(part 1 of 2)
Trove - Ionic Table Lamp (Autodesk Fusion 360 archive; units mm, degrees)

design "Marble Base - Ionic Table Lamp - 120V" references "Marble Base - Silicone Gasket", "Balon v2", "Chinois", "Neoprene Pad", "Rubber Grommet", "Marble Base - Plastic Insert", "2-Pole Plug End", "Trove - TL", "Arca Tall", "T9 - Bulb", "Facet Petite", "T9-5In"
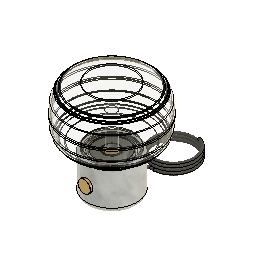
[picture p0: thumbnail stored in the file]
sketch "Sketch1" plane through (0, 0, 0) normal (0, 0, 1) x axis (1, 0, 0)
  circle C1 centre (0, 0) radius 63.5
  point P1 (0, 0)
  point P2 (0, 0)
  coincident P1 P2
extrude "Extrude1" new body sketch "Sketch1" along normal blind 101.6 bodies "Marble Base"
sketch "Sketch2" plane through (0, 0, 101.6) normal (0, 0, 1) x axis (-1, 0, 0)
  circle C1 centre (0, 0) radius 63.5
  circle C2 centre (0, 0) radius 53.975
  concentric C1 C2
  dimension "d3" diameter C2 = 107.95
extrude "Extrude2" cut sketch "Sketch2" profile of C2 against normal blind 34.925
sketch "Sketch3" plane through (0, 0, 66.675) normal (0, 0, 1) x axis (-1, 0, 0)
  circle C1 centre (0, 0) radius 53.975
  circle C2 centre (0, 0) radius 49.276
  point P1 (0, 0)
  point P3 (0, 0)
  coincident P1 P3
  dimension "d6" diameter C2 = 98.552
extrude "Extrude3" cut sketch "Sketch3" profile of C2 against normal blind 45.72
sketch "Sketch4" plane through (0, 0, 0) normal (0, 1, 0) x axis (1, 0, 0)
  circle C1 centre (0, -50.8) radius 3.81
  dimension "d9" diameter C1 = 7.62
extrude "Extrude4" cut sketch "Sketch4" against normal blind 127
sketch "Sketch5" plane through (0, 0, 0) normal (0, 1, 0) x axis (1, 0, 0)
  line L1 (0, -25.4) -> (0, 0)
  line L2 (0, -30.48) -> (0, -25.4)
  circle C1 centre (0, -30.48) radius 5.08
  point P1 (0, 0)
  point P2 (0, 0)
  point P4 (0, -30.48)
  point P5 (0, -30.48)
  coincident P1 P2
  vertical L1
  parallel L1 L2
  coincident P4 P5
  dimension "d12" diameter C1 = 10.16
extrude "Extrude5" cut sketch "Sketch5" profile of C1 along normal blind 114.3
fillet "Fillet1" radius 6.35 3.175 4.064
derived_base_feature "Derived Base Feature1" bodies "Rotary Switch"
derived_base_feature "Derived Base Feature1" bodies "Coiled - SVT (Blk Fabric)"
derived_base_feature "Derived Base Feature1" bodies "Glass Globe"
derived_base_feature "Derived Base Feature1" bodies "Metal Housing"
derived_base_feature "Derived Base Feature1" bodies "Metal Socket Cover"
derived_base_feature "Derived Base Feature1" bodies "Porcelain Socket"
derived_base_feature "Derived Base Feature1" bodies "Brass Dial - Dimmer Knob"
component_from_bodies "Body->Comp1"
offset_faces "OffsetFaces1" distance 12.7
offset_faces "OffsetFaces2" distance -12.7
derived_base_feature "Derived Base Feature1" bodies "Solitaire Petite"
move "Move1"
offset_faces "OffsetFaces1" distance 20.32
move "Move2"
extrude "Extrude6" add of existing geometry blind 25.4
offset_faces "OffsetFaces2" distance -3.81
fillet "Fillet2" radius 2.54
move "Move3"
derived_base_feature "Derived Base Feature2" bodies "Facet Petite"
move "Move4"
offset_faces "OffsetFaces1" distance 2.54
move "Move1"
derived_base_feature "Derived Base Feature1" bodies "Body1"
derived_base_feature "Derived Base Feature1" bodies "Body1"
derived_base_feature "Derived Base Feature1" bodies "Body1"
derived_base_feature "Derived Base Feature1" bodies "Body1"
derived_base_feature "Derived Base Feature1" bodies "Body1"
derived_base_feature "Derived Base Feature1" bodies "Body1", "Body2"
derived_base_feature "Derived Base Feature1" bodies "Body1"
position "Position1"
external_derived "ExternalDerived5" bodies "Plastic Insert"
derived_instance "DerivedInstance15"
offset_faces "OffsetFaces1" distance 3.81
offset_faces "OffsetFaces2" distance -1.0414
move "Move6"
external_derived "ExternalDerived6" sketch "Sketch3" bodies "Silicone Gasket"
derived_instance "DerivedInstance16"
offset_faces "OffsetFaces3" distance -10.795
move "Move1"
move_face "MoveFace1"
position "Position2"
position "Position3"
position "Position4"
position "Position5"
move "Move2"
position "Position6"
offset_faces "OffsetFaces2" distance -7.62
chamfer "Chamfer1" distance 0.381
remove_instance "RemoveInstance1"
remove_instance "RemoveInstance2"
remove_instance "RemoveInstance3"
remove_instance "RemoveInstance4"
move "Move1"
derived_base_feature "Derived Base Feature5" bodies "Oculo Petite"
align "Align1"
external_derived "ExternalDerived8"
derived_base_feature "Derived Base Feature7" bodies "Balon v2"
derived_base_feature "Derived Base Feature8" bodies "Balon v3"
align "Align3"
align "Align4"
external_derived "ExternalDerived10"
component_insert "Component Insert1"
position "Position7"
position "Position8"
derived_base_feature "Derived Base Feature11" bodies "Trove - TL"
move "Move10"
move "Move11"
remove_instance "RemoveInstance5"
split "Split1" bodies "Trove - TL (1)"
remove_body "RemoveBody2"
remove_body "RemoveBody3"
external_derived "ExternalDerived13" bodies "Trove - TL"
derived_instance "DerivedInstance20"
remove_body "RemoveBody4"
remove_body "RemoveBody5"
component_insert "Component Insert2"
component_insert "Component Insert3"
component_from_bodies "Body->Comp2"
remove_body "RemoveBody7"
move "Move12"
move "Move13"
sketch "Sketch6" plane through (0, 0, 97.917) normal (0, 0, 1) x axis (-1, 0, 0)
  circle C1 centre (0, 0) radius 41.275
  circle C2 centre (0, 0) radius 19.685
  arc A1 centre (0, 0) radius 29.3982 clockwise from (-27.6283, 10.0466) to (27.6283, 10.0466)
  arc A2 centre (0, 0) radius 26.2232 clockwise from (-24.6444, 8.9616) to (24.6444, 8.9616)
  arc A3 centre (0, 0) radius 32.5732 clockwise from (-30.6121, 11.1317) to (30.6121, 11.1317)
  arc A4 centre (0, 0) radius 35.7482 clockwise from (-33.596, 12.2167) to (33.596, 12.2167)
  point P1 (0, 0)
  point P3 (0, 0)
  coincident P1 P3
  dimension "d37" = -3.175
  dimension "d38" = 3.175
  dimension "d39" = 6.35
  dimension "d40" Text1-Height = 2.54
  dimension "d41" Text2-Height = 2.54
  dimension "d42" Text3-Height = 2.54
  dimension "d43" Text4-Height = 2.54
extrude "Extrude1" cut sketch "Sketch6" against normal blind 0.254
external_derived "ExternalDerived14" bodies "Rubber Grommet"
derived_instance "DerivedInstance19"
external_derived "ExternalDerived15" bodies "2-Pole Plug End"
derived_instance "DerivedInstance18"
external_derived "ExternalDerived16" bodies "Neoprene Pad"
derived_instance "DerivedInstance17"
position "Position9"
position "Position10"
position "Position11"
position "Position12"
external_derived "ExternalDerived17" bodies "Chinois"
derived_instance "DerivedInstance21"
position "Position13"
move "Move3"
remove_body "RemoveBody8"
component_insert "Component Insert4"
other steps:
derived_base_feature "Derived Base Feature1" bodies "Trove - TL"
derived_base_feature "Derived Base Feature1" bodies "Chinois"
derived_base_feature "Derived Base Feature1" bodies "Rubber Grommet"
derived_base_feature "Derived Base Feature1" bodies "2-Pole Plug End"
derived_base_feature "Derived Base Feature1" bodies "Neoprene Pad"
move "Move1"
base_feature "Base Feature1" bodies "Oculo Petite", "Arca Petite"
derived_base_feature "Derived Base Feature1" bodies "Plastic Insert"
derived_base_feature "Derived Base Feature1" bodies "Silicone Gasket"
base_feature "Base Feature1" bodies "Marble Base"
move "Move8"
derived_base_feature "Derived Base Feature"
create_component "CreateComponent1"
create_component "CreateComponent2"
create_component "CreateComponent3"
create_component "CreateComponent4"
create_component "CreateComponent5"
create_component "CreateComponent6"
create_component "CreateComponent7"
create_component "CreateComponent8"
remove_body "RemoveBody1"
create_component "CreateComponent9"
create_component "CreateComponent10"
create_component "CreateComponent11"
create_component "CreateComponent12"
create_component "CreateComponent13"
create_component "CreateComponent14"
create_component "CreateComponent15"
create_component "CreateComponent16"
create_component "CreateComponent17"
create_component "CreateComponent18"
remove_body "RemoveBody6"
create_component "CreateComponent19"
create_component "CreateComponent20"
create_component "CreateComponent21"
create_component "CreateComponent22"
create_component "CreateComponent23"
named bodies: "Marble Base", "Rotary Switch", "Coiled - SVT (Blk Fabric)", "Glass Globe", "Metal Housing", "Metal Socket Cover", "Porcelain Socket", "Brass Dial - Dimmer Knob", "Solitaire Petite", "Facet Petite", "Body1", "Body2", "Plastic Insert", "Silicone Gasket", "Oculo Petite", "Balon v2", "Balon v3", "Trove - TL", "Trove - TL (1)", "Arca Petite", "Neoprene Pad", "2-Pole Plug End", "Rubber Grommet", "Chinois"

design "Neoprene Pad"
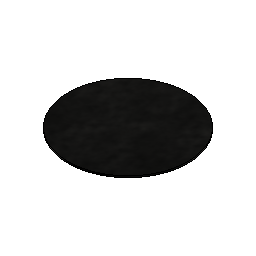
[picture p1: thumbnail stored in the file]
sketch "Sketch1" plane through (0, 0, 0) normal (0, 0, 1) x axis (1, 0, 0)
  circle C1 centre (0, 0) radius 57.15
  point P1 (0, 0)
  point P2 (0, 0)
  coincident P1 P2
extrude "Extrude1" new body sketch "Sketch1" along normal blind 1.5875 bodies "Neoprene Pad"
component_from_bodies "Body->Comp"
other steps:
base_feature "Base Feature" bodies "Neoprene Pad"
create_component "CreateComponent1"
remove_body "RemoveBody1"
named bodies: "Neoprene Pad"

design "T9 - Bulb"
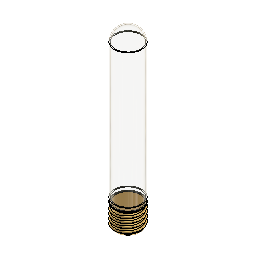
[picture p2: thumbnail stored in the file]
sketch "Sketch1" plane through (0, 0, 0) normal (0, 1, 0) x axis (1, 0, 0)
  line L1 (0, -166.37) -> (0, 0)
  line L2 (13.97, -13.97) -> (13.97, -152.4)
  line L3 (-13.97, -152.4) -> (-13.97, -13.97)
  line L4 (0, 0) -> (0, -166.37)
  line L5 (12.97, -13.97) -> (12.97, -152.4)
  line L6 (-12.97, -152.4) -> (-12.97, -13.97)
  line L7 (-12.3978, -10.16) -> (-13.4404, -10.16)
  line L8 (13.4404, -10.16) -> (12.3978, -10.16)
  arc A1 centre (0, -152.4) radius 13.97 clockwise from (13.97, -152.4) to (-13.97, -152.4)
  arc A2 centre (0, -152.4) radius 12.97 clockwise from (12.97, -152.4) to (-12.97, -152.4)
  arc A3 centre (0, -13.97) radius 13.97 clockwise from (13.4404, -10.16) to (13.97, -13.97)
  arc A4 centre (0, -13.97) radius 13.97 clockwise from (-13.97, -13.97) to (-13.4404, -10.16)
  arc A5 centre (0, -13.97) radius 12.97 clockwise from (12.3978, -10.16) to (12.97, -13.97)
  arc A6 centre (0, -13.97) radius 12.97 clockwise from (-12.97, -13.97) to (-12.3978, -10.16)
  point P1 (0, 0)
  point P2 (0, 0)
  point P3 (0, -166.37)
  point P10 (0, 0)
  point P17 (13.4404, -10.16)
  point P19 (12.3978, -10.16)
  point P4 (13.97, -152.4)
  point P5 (13.97, -13.97)
  coincident P1 P2
  vertical L1
  tangent L2 A3
  tangent L3 A3
  parallel L2 L3
  tangent L3 A1
  tangent L2 A1
  midpoint P3 A1
  coincident P1 P10
  perpendicular L1 L7
  coincident P17 L7
  concentric A3 A4
  coincident P10 A3
  concentric A1 A2
  tangent L5 A2
  tangent L5 A5
  tangent L6 A5
  tangent L6 A2
  coincident P19 L7
  concentric A5 A6
  collinear L7 L8
  dimension "d6" distance L2 L3 = 27.94
  dimension "d7" distance P4 P5 = 138.43
revolve "Revolve1" sketch "Sketch1" AlongAngle 360 bodies "T9"
derived_base_feature "Derived Base Feature" bodies "E26 Base"
align "Align1"
move "Move1"
component_from_bodies "Body->Comp1"
component_from_bodies "Body->Comp2"
copy_paste "CutPaste1"
copy_paste "CutPaste2"
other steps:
base_feature "Base Feature1" bodies "T9"
base_feature "Base Feature1" bodies "E26 Base"
create_component "CreateComponent1"
create_component "CreateComponent2"
remove_body "RemoveBody1"
create_component "CreateComponent3"
remove_body "RemoveBody2"
remove_instance "RemoveInstance1"
remove_instance "RemoveInstance2"
named bodies: "T9", "E26 Base"

design "Marble Base - Silicone Gasket"
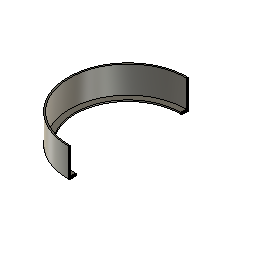
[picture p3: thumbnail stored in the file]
sketch "Sketch1" plane through (0, 0, 0) normal (0, 0, 1) x axis (1, 0, 0)
  circle C1 centre (0, 0) radius 53.34
  point P1 (0, 0)
  point P2 (0, 0)
  coincident P1 P2
extrude "Extrude1" new body sketch "Sketch1" along normal blind 25.4 bodies "Silicone Gasket"
shell "Shell1" innerThickness 1.27
sketch "Sketch2" plane through (0, 0, 1.27) normal (0, 0, 1) x axis (-1, 0, 0)
  circle C1 centre (0, 0) radius 52.07
  circle C2 centre (0, 0) radius 46.99
  concentric C1 C2
extrude "Extrude2" cut sketch "Sketch2" profile of C2 against normal blind 12.7
component_from_bodies "Body->Comp"
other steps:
base_feature "Base Feature" bodies "Silicone Gasket"
create_component "CreateComponent1"
remove_body "RemoveBody1"
named bodies: "Silicone Gasket"

design "2-Pole Plug End"
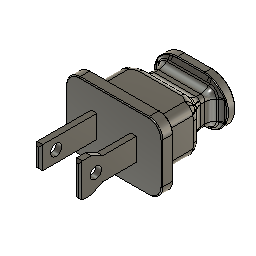
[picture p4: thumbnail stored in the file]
sketch "Sketch1" plane through (0, 0, 0) normal (0, 1, 0) x axis (1, 0, 0)
  line L1 (9.6837, 9.525) -> (-9.6837, 9.525)
  line L2 (13.4938, -5.715) -> (13.4938, 5.715)
  line L3 (-9.6837, -9.525) -> (9.6837, -9.525)
  line L4 (-13.4937, 5.715) -> (-13.4937, -5.715)
  line L5 (13.4938, -9.525) -> (-13.4937, 9.525)
  line L6 (-13.4937, -9.525) -> (13.4938, 9.525)
  arc A1 centre (-9.6837, -5.715) radius 3.81 clockwise from (-9.6837, -9.525) to (-13.4937, -5.715)
  arc A2 centre (9.6837, -5.715) radius 3.81 clockwise from (13.4938, -5.715) to (9.6837, -9.525)
  arc A3 centre (9.6837, 5.715) radius 3.81 clockwise from (9.6837, 9.525) to (13.4938, 5.715)
  arc A4 centre (-9.6837, 5.715) radius 3.81 clockwise from (-13.4937, 5.715) to (-9.6837, 9.525)
  point P6 (0, 0)
  point P1 (0, 0)
  point P5 (-13.4937, -9.525)
  point P4 (13.4938, -9.525)
  point P3 (13.4938, 9.525)
  point P2 (-13.4937, 9.525)
  horizontal L1
  perpendicular L1 L2
  parallel L1 L3
  parallel L2 L4
  coincident L5 P6
  coincident L6 P6
  coincident P1 P6
  coincident P5 L4
  coincident P5 L3
  tangent L4 A1
  tangent L3 A1
  coincident P4 L3
  coincident P4 L2
  tangent L3 A2
  tangent L2 A2
  equal A1 A2
  coincident P3 L2
  coincident P3 L1
  tangent L2 A3
  tangent L1 A3
  equal A1 A3
  coincident P2 L1
  coincident P2 L4
  tangent L1 A4
  tangent L4 A4
  equal A1 A4
  dimension "d1" distance P4 P5 = 26.9875
  dimension "d2" distance P2 P5 = 19.05
  dimension "d3" radius A1 = 3.81
extrude "Extrude1" new body sketch "Sketch1" profile of L1 L2 L3 L4 A1 A2 A3 A4 along normal blind 3.175
sketch "Sketch2" plane through (0, 3.175, 0) normal (0, 1, 0) x axis (-1, 0, 0)
  line L1 (9.6837, -9.525) -> (-9.6837, -9.525)
  line L2 (13.4937, 5.715) -> (13.4937, -5.715)
  line L3 (-9.6837, 9.525) -> (9.6837, 9.525)
  line L4 (-13.4938, -5.715) -> (-13.4938, 5.715)
  line L5 (10.16, -6.35) -> (-10.16, -6.35)
  line L6 (10.16, 6.35) -> (10.16, -6.35)
  line L7 (-10.16, 6.35) -> (10.16, 6.35)
  line L8 (-10.16, -6.35) -> (-10.16, 6.35)
  line L9 (10.16, 6.35) -> (-10.16, -6.35)
  line L10 (-10.16, 6.35) -> (10.16, -6.35)
  arc A1 centre (-9.6837, -5.715) radius 3.81 clockwise from (-9.6837, -9.525) to (-13.4938, -5.715)
  arc A2 centre (9.6837, -5.715) radius 3.81 clockwise from (13.4937, -5.715) to (9.6837, -9.525)
  arc A3 centre (9.6837, 5.715) radius 3.81 clockwise from (9.6837, 9.525) to (13.4937, 5.715)
  arc A4 centre (-9.6837, 5.715) radius 3.81 clockwise from (-13.4938, 5.715) to (-9.6837, 9.525)
  point P18 (0, 0)
  point P1 (0, 0)
  horizontal L5
  perpendicular L5 L6
  parallel L5 L7
  parallel L6 L8
  coincident L9 P18
  coincident L10 P18
  coincident P1 P18
extrude "Extrude2" add sketch "Sketch2" profile of L5 L6 L7 L8 along normal blind 9.525
sketch "Sketch3" plane through (0, 12.7, 0) normal (0, 1, 0) x axis (-1, 0, 0)
  line L1 (-10.16, -6.35) -> (-10.16, 6.35)
  line L2 (10.16, -6.35) -> (-10.16, -6.35)
  line L3 (10.16, 6.35) -> (10.16, -6.35)
  line L4 (-10.16, 6.35) -> (10.16, 6.35)
  line L5 (-7.1437, 3.9688) -> (7.1437, 3.9688)
  line L6 (-7.1437, -3.9688) -> (-7.1437, 3.9688)
  line L7 (7.1437, -3.9688) -> (-7.1437, -3.9688)
  line L8 (7.1437, 3.9688) -> (7.1437, -3.9688)
  line L9 (-7.1437, -3.9688) -> (7.1437, 3.9688)
  line L10 (7.1437, -3.9688) -> (-7.1437, 3.9688)
  point P10 (0, 0)
  point P1 (0, 0)
  point P8 (-7.1437, -3.9688)
  point P9 (7.1437, -3.9688)
  point P7 (-7.1437, 3.9688)
  horizontal L5
  perpendicular L5 L6
  parallel L5 L7
  parallel L6 L8
  coincident L9 P10
  coincident L10 P10
  coincident P1 P10
  dimension "d8" distance P8 P9 = 14.2875
  dimension "d9" distance P7 P8 = 7.9375
extrude "Extrude3" add sketch "Sketch3" profile of L5 L6 L7 L8 along normal blind 11.1125
fillet "Fillet1" radius 2.286 1.27 0.254
chamfer "Chamfer1" distance 3.429
fillet "Fillet2" radius 2.54 1.905
sketch "Sketch4" plane through (0, 23.8125, 0) normal (0, 1, 0) x axis (-1, 0, 0)
  line L1 (-7.1437, -2.6987) -> (-7.1437, 2.6987)
  line L2 (5.8737, -3.9688) -> (-5.8737, -3.9688)
  line L3 (7.1437, 2.6987) -> (7.1437, -2.6987)
  line L4 (-5.8737, 3.9688) -> (5.8737, 3.9688)
  line L5 (-3.81, 6.604) -> (3.81, 6.604)
  line L6 (3.81, -6.604) -> (-3.81, -6.604)
  line L7 (-10.414, 0) -> (10.414, 0)
  arc A1 centre (-5.8737, 2.6987) radius 1.27 clockwise from (-7.1437, 2.6987) to (-5.8737, 3.9688)
  arc A2 centre (-5.8737, -2.6987) radius 1.27 clockwise from (-5.8737, -3.9688) to (-7.1437, -2.6987)
  arc A3 centre (5.8737, -2.6987) radius 1.27 clockwise from (7.1437, -2.6987) to (5.8737, -3.9688)
  arc A4 centre (5.8737, 2.6987) radius 1.27 clockwise from (5.8737, 3.9688) to (7.1437, 2.6987)
  arc A5 centre (-3.81, 0) radius 6.604 clockwise from (-3.81, -6.604) to (-3.81, 6.604)
  arc A6 centre (3.81, 0) radius 6.604 clockwise from (3.81, 6.604) to (3.81, -6.604)
  point P20 (10.414, 0)
  point P21 (-10.414, 0)
  tangent L5 A5
  tangent A5 L6
  parallel L5 L6
  tangent L6 A6
  tangent L5 A6
  midpoint A6 P20
  midpoint A5 P21
  perpendicular L1 L7
extrude "Extrude4" add sketch "Sketch4" profile of A1 L1 A2 L2 A3 L3 A4 L4 L5 A5 L6 A6 against normal blind 2.286
chamfer "Chamfer2" distance 1.778
fillet "Fillet3" radius 1.778
fillet "Fillet4" radius 0.254
fillet "Fillet5" radius 0.254
fillet "Fillet6" radius 0.254
fillet "Fillet7" radius 3.175
sketch "Sketch5" plane through (0, 0, 0) normal (0, -1, 0) x axis (1, 0, 0)
  line L1 (-13.2397, -5.715) -> (-13.2397, 5.715)
  line L2 (9.6837, -9.271) -> (-9.6837, -9.271)
  line L3 (13.2397, 5.715) -> (13.2397, -5.715)
  line L4 (-9.6837, 9.271) -> (9.6837, 9.271)
  line L5 (-6.35, -3.175) -> (-6.35, 3.175)
  line L6 (6.35, 3.175) -> (-6.35, -3.175)
  line L7 (-6.35, 3.175) -> (6.35, -3.175)
  line L8 (-4.7625, 3.175) -> (-6.35, 3.175)
  line L9 (-4.7625, -3.175) -> (-4.7625, 3.175)
  line L10 (-6.35, -3.175) -> (-4.7625, -3.175)
  line L11 (-6.35, 3.175) -> (-6.35, -3.175)
  line L12 (0, -3.302) -> (0, 3.81)
  line L13 (4.7625, -3.175) -> (4.7625, 3.175)
  line L14 (4.7625, 3.175) -> (6.35, 3.175)
  line L15 (6.35, -3.175) -> (6.35, 3.175)
  line L16 (6.35, -3.175) -> (4.7625, -3.175)
  arc A1 centre (-9.6837, 5.715) radius 3.556 clockwise from (-13.2397, 5.715) to (-9.6837, 9.271)
  arc A2 centre (-9.6837, -5.715) radius 3.556 clockwise from (-9.6837, -9.271) to (-13.2397, -5.715)
  arc A3 centre (9.6837, -5.715) radius 3.556 clockwise from (13.2397, -5.715) to (9.6837, -9.271)
  arc A4 centre (9.6837, 5.715) radius 3.556 clockwise from (9.6837, 9.271) to (13.2397, 5.715)
  point P18 (0, 0)
  point P1 (0, 0)
  point P14 (-6.35, -3.175)
  point P27 (6.35, -3.175)
  point P17 (-6.35, 3.175)
  point P26 (6.35, 3.175)
  point P19 (-4.7625, 3.175)
  point P24 (4.7625, 3.175)
  point P20 (-4.7625, -3.175)
  point P25 (4.7625, -3.175)
  point P21 (-6.35, -3.175)
  point P28 (6.35, -3.175)
  point P15 (6.35, -3.175)
  point P16 (6.35, 3.175)
  coincident L6 P18
  coincident L7 P18
  coincident P1 P18
  horizontal L8
  vertical L9
  horizontal L10
  vertical L11
  vertical L12
  symmetric P14 L12 P27
  symmetric P17 L12 P26
  symmetric P19 L12 P24
  symmetric P20 L12 P25
  symmetric P21 L12 P28
  dimension "d36" distance P15 P16 = 6.35
  dimension "d37" distance P17 P19 = 1.5875
extrude "Extrude5" add sketch "Sketch5" profile of L5 L8 L9 L10 L11 L13 L14 L15 L16 along normal blind 15.875
sketch "Sketch7" plane through (0, 0, 3.175) normal (0, 0, 1) x axis (-1, 0, 0)
  line L1 (-4.7625, 0) -> (-6.35, 0)
  line L2 (-4.7625, 15.875) -> (-4.7625, 0)
  line L3 (-6.35, 15.875) -> (-4.7625, 15.875)
  line L4 (-6.35, 0) -> (-6.35, 15.875)
  line L5 (-4.7625, 15.875) -> (-6.35, 15.875)
  line L6 (-4.7625, 9.525) -> (-4.7625, 15.875)
  line L7 (-6.35, 9.525) -> (-4.7625, 9.525)
  line L8 (-6.35, 15.875) -> (-6.35, 9.525)
  point P5 (-6.35, 15.875)
  point P6 (-6.35, 15.875)
  point P9 (-6.35, 9.525)
  horizontal L5
  vertical L6
  horizontal L7
  vertical L8
  coincident P5 P6
  dimension "d45" distance P6 P9 = 6.35
extrude "Extrude7" add sketch "Sketch7" profile of L2 L3 L4 L5 L6 L7 L8 against normal blind 7.9375 and along normal blind 1.5875
chamfer "Chamfer3" distance 0.508
chamfer "Chamfer4" distance 0.635 distance 0.635
sketch "Sketch6" plane through (6.35, 0, 0) normal (1, 0, 0) x axis (0, 1, 0)
  line L1 (0, -3.175) -> (-9.525, -3.175)
  line L2 (0, 3.175) -> (0, -3.175)
  line L3 (-9.525, 3.175) -> (0, 3.175)
  line L4 (-15.367, -4.6355) -> (-15.367, 4.6355)
  line L5 (-11.43, 0) -> (-16.002, 0)
  line L6 (-9.525, -4.7625) -> (-15.24, -4.7625)
  line L7 (-9.525, -3.175) -> (-9.525, -4.7625)
  line L8 (-9.525, 4.7625) -> (-9.525, 3.175)
  line L9 (-15.24, 4.7625) -> (-9.525, 4.7625)
  line L10 (-15.24, -4.7625) -> (-15.367, -4.6355)
  line L11 (-15.367, 4.6355) -> (-15.24, 4.7625)
  circle C1 centre (-11.43, 0) radius 1.5875
  point P9 (-11.43, 0)
  point P10 (-11.43, 0)
  perpendicular L4 L5
  coincident P9 P10
  dimension "d42" diameter C1 = 3.175
extrude "Extrude6" cut sketch "Sketch6" profile of C1 against normal blind 20.32
chamfer "Chamfer5" distance 3.175 distance 1.5875 distance 3.175 distance 1.5875
component_from_bodies "Body->Comp"
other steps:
base_feature "Base Feature" bodies "2-Pole Plug End"
create_component "CreateComponent1"
remove_body "RemoveBody1"
named bodies: "2-Pole Plug End"

design "Facet Petite"
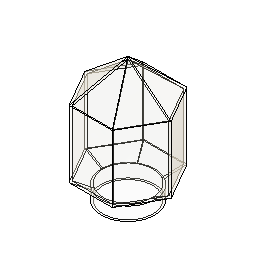
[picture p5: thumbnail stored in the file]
sketch "Sketch7" plane through (0, 0, 0) normal (1, 0, 0) x axis (0, 1, 0)
sketch "Sketch8" plane through (0, 0, 0) normal (0, 0, 1) x axis (1, 0, 0)
  circle C1 centre (0, 0) radius 50.8
  point P1 (0, 0)
  point P2 (0, 0)
  coincident P1 P2
  dimension "d17" diameter C1 = 101.6
extrude "Extrude5" new body sketch "Sketch8" along normal blind 25.4 and against normal blind 25.4
work_plane "WorkPlane1" AlongDistance 17.78
sketch "Sketch10" plane through (0, 0, 25.4) normal (0, 0, 1) x axis (-1, 0, 0)
  circle C1 centre (0, 0) radius 50.8
sketch "Sketch12" plane through (0, 0, 43.18) normal (0, 0, 1) x axis (1, 0, 0)
  line L1 (-82.1223, 0) -> (-41.0612, 71.12)
  line L2 (-41.0612, -71.12) -> (-82.1223, 0)
  line L3 (41.0612, -71.12) -> (-41.0612, -71.12)
  line L4 (82.1223, 0) -> (41.0612, -71.12)
  line L5 (41.0612, 71.12) -> (82.1223, 0)
  line L6 (-41.0612, 71.12) -> (41.0612, 71.12)
  point P1 (0, 0)
  point P8 (0, 0)
  coincident P1 P8
  dimension "d22" distance P8 L6 = 71.12
sketch "Sketch15" plane through (0, 0, 0) normal (0, 1, 0) x axis (1, 0, 0)
  line L1 (53.7365, -21.6801) -> (82.1223, -43.18)
  line L2 (-50.8, -25.4) -> (-82.1223, -43.18)
  point P2 (82.1223, -43.18)
  point P3 (82.1223, -43.18)
  point P5 (-82.1223, -43.18)
  point P7 (-82.1223, -43.18)
  point P6 (-50.8, -25.4)
  point P8 (-50.8, -25.4)
  coincident P2 P3
  coincident P5 P7
  coincident P6 P8
sketch "Sketch17" plane through (0, 0, 25.4) normal (0, 0, 1) x axis (-1, 0, 0)
  line L1 (51.3255, 0) -> (0, 0)
  line L2 (73.3235, 0) -> (0, 0)
  line L3 (-41.0612, -71.12) -> (-25.4, -43.9941)
  line L4 (-36.6617, -63.5) -> (-25.4, -43.9941)
  line L5 (78.4305, 0) -> (0, 0)
  line L6 (41.0612, -71.12) -> (25.4, -43.9941)
  line L7 (25.4, 43.9941) -> (41.0612, 71.12)
  line L8 (73.3235, 0) -> (0, 0)
  line L9 (-25.4, 43.9941) -> (-41.0612, 71.12)
  line L10 (0, 0) -> (0, 0)
  circle C1 centre (0, 0) radius 50.8
  point P1 (0, 0)
  point P4 (0, 0)
  point P2 (-41.0612, -71.12)
  point P6 (-41.0612, -71.12)
  point P3 (0, 0)
  point P7 (0, 0)
  point P9 (-25.4, -43.9941)
  point P12 (41.0612, -71.12)
  point P13 (41.0612, -71.12)
  point P15 (25.4, -43.9941)
  point P16 (41.0612, 71.12)
  point P17 (41.0612, 71.12)
  point P18 (25.4, 43.9941)
  point P19 (-41.0612, 71.12)
  point P20 (-41.0612, 71.12)
  point P21 (0, 0)
  point P23 (-25.4, 43.9941)
  point P25 (0, 0)
  point P24 (0, 0)
  point P26 (0, 0)
  horizontal L1
  coincident P1 P4
  coincident P2 P6
  horizontal L2
  coincident P3 P7
  coincident C1 P9
  coincident P12 P13
  horizontal L5
  coincident C1 P15
  coincident P16 P17
  coincident C1 P18
  coincident P19 P20
  horizontal L8
  coincident P1 P21
  coincident C1 P23
  coincident P1 P25
  coincident P24 P26
extrude "Extrude6" new body sketch "Sketch12" along normal blind 127
work_plane "WorkPlane2" AlongDistance 66.04
sketch "Sketch18" plane through (0, 0, 236.22) normal (0, 0, 1) x axis (1, 0, 0)
  line L1 (41.0612, -71.12) -> (0, 0)
  line L2 (82.1223, 0) -> (0, 0)
  line L3 (41.0612, 71.12) -> (0, 0)
  line L4 (-41.0612, 71.12) -> (0, 0)
  line L5 (-82.1223, 0) -> (0, 0)
  line L6 (-41.0612, -71.12) -> (0, 0)
  point P1 (0, 0)
  point P3 (0, 0)
  point P2 (41.0612, -71.12)
  point P4 (41.0612, -71.12)
  point P6 (0, 0)
  point P5 (82.1223, 0)
  point P7 (82.1223, 0)
  point P9 (0, 0)
  point P8 (41.0612, 71.12)
  point P10 (41.0612, 71.12)
  point P12 (0, 0)
  point P11 (-41.0612, 71.12)
  point P13 (-41.0612, 71.12)
  point P15 (0, 0)
  point P14 (-82.1223, 0)
  point P16 (-82.1223, 0)
  point P18 (0, 0)
  point P17 (-41.0612, -71.12)
  point P19 (-41.0612, -71.12)
  coincident P1 P3
  coincident P2 P4
  coincident P1 P6
  coincident P5 P7
  coincident P1 P9
  coincident P8 P10
  coincident P1 P12
  coincident P11 P13
  coincident P1 P15
  coincident P14 P16
  coincident P1 P18
  coincident P17 P19
loft "Loft1"
loft "Loft2" sketch "Sketch17"
component_from_bodies "Body->Comp"
extrude "Extrude1" cut of existing geometry blind -25.4
shell "Shell2" innerThickness 3.81
fillet "Fillet1" radius 7.62
fillet "Fillet2" radius 6.35
fillet "Fillet3" radius 6.35
fillet "Fillet4" radius 6.35
fillet "Fillet5" radius 6.35
fillet "Fillet6" radius 6.35
fillet "Fillet7" radius 3.81
fillet "Fillet8" radius 6.35
fillet "Fillet9" radius 6.35
fillet "Fillet10" radius 6.35
fillet "Fillet11" radius 6.35
fillet "Fillet12" radius 6.35
fillet "Fillet13" radius 2.286
shell "Shell1" innerThickness 2.54
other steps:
base_feature "Base Feature"
create_component "CreateComponent3"
remove_body "RemoveBody2"

design "Chinois"
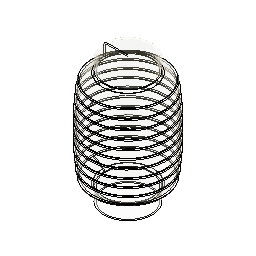
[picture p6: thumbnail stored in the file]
named bodies: "Chinois"

design "Marble Base - Plastic Insert"
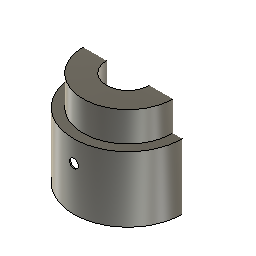
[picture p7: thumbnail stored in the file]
sketch "Sketch1" plane through (0, 0, 0) normal (0, 0, 1) x axis (1, 0, 0)
  circle C1 centre (0, 0) radius 50.038
  point P1 (0, 0)
  point P2 (0, 0)
  coincident P1 P2
  dimension "d1" diameter C1 = 100.076
extrude "Extrude1" new body sketch "Sketch1" along normal blind 72.898 bodies "Plastic Insert"
shell "Shell1" innerThickness 1.016
work_plane "WorkPlane1" AlongDistance 18.034
sketch "Sketch2" plane through (0, 0, 90.932) normal (0, 0, 1) x axis (1, 0, 0)
  circle C1 centre (0, 0) radius 20.701
  point P1 (0, 0)
  point P2 (0, 0)
  coincident P1 P2
  dimension "d6" diameter C1 = 41.402
extrude "Extrude2" add sketch "Sketch2" against normal blind 65.024
shell "Shell2" innerThickness 1.016
sketch "Sketch3" plane through (0, 0, 0) normal (0, 1, 0) x axis (1, 0, 0)
  line L1 (5.08, -20.32) -> (-5.08, -20.32)
  line L2 (5.08, 20.32) -> (5.08, -20.32)
  line L3 (-5.08, 20.32) -> (5.08, 20.32)
  line L4 (-5.08, -20.32) -> (-5.08, 20.32)
  line L5 (5.08, 20.32) -> (-5.08, -20.32)
  line L6 (-5.08, 20.32) -> (5.08, -20.32)
  point P6 (0, 0)
  point P1 (0, 0)
  horizontal L1
  perpendicular L1 L2
  parallel L1 L3
  parallel L2 L4
  coincident L5 P6
  coincident L6 P6
  coincident P1 P6
extrude "Extrude3" cut sketch "Sketch3" profile of L1 L2 L3 L4 along normal blind 91.44
sketch "Sketch4" plane through (0, 0, 0) normal (0, 1, 0) x axis (1, 0, 0)
  line L1 (0, -40.64) -> (0, 0)
  circle C1 centre (0, -40.64) radius 4.064
  point P1 (0, 0)
  point P2 (0, 0)
  point P3 (0, -40.64)
  point P4 (0, -40.64)
  coincident P1 P2
  vertical L1
  coincident P3 P4
  dimension "d12" diameter C1 = 8.128
work_plane "WorkPlane2" AlongDistance -91.44
sketch "Sketch5" plane through (0, -91.44, 0) normal (0, 1, 0) x axis (1, 0, 0)
  circle C1 centre (0, -40.64) radius 4.064
extrude "Extrude4" cut sketch "Sketch5" along normal blind 63.5
sketch "Sketch6" plane through (0, 0, 26.924) normal (0, 0, 1) x axis (-1, 0, 0)
  circle C1 centre (0, 0) radius 19.685
  circle C2 centre (0, 0) radius 5.461
  concentric C1 C2
  dimension "d16" diameter C2 = 10.922
extrude "Extrude5" cut sketch "Sketch6" profile of C2 against normal blind 15.24
sketch "Sketch7" plane through (0, 0, 72.898) normal (0, 0, 1) x axis (-1, 0, 0)
  circle C1 centre (0, 0) radius 20.701
  circle C2 centre (0, 0) radius 50.038
  circle C3 centre (0, 0) radius 20.701
  circle C4 centre (0, 0) radius 45.72
  point P1 (0, 0)
  point P3 (0, 0)
  point P4 (0, 0)
  coincident P1 P3
  coincident P1 P4
extrude "Extrude6" add sketch "Sketch7" profile of C1 C3 C4 along normal blind 18.034
sketch "Sketch8" plane through (0, 0, 71.882) normal (0, 0, -1) x axis (1, 0, 0)
  circle C1 centre (0, 0) radius 20.701
  circle C2 centre (0, 0) radius 49.022
  circle C3 centre (0, 0) radius 20.701
  circle C4 centre (0, 0) radius 44.704
  point P1 (0, 0)
  point P3 (0, 0)
  point P4 (0, 0)
  coincident P1 P3
  coincident P1 P4
  dimension "d21" diameter C4 = 89.408
extrude "Extrude7" cut sketch "Sketch8" profile of C1 C3 C4 against normal blind 17.78
extrude "Extrude8" add of existing geometry blind 9.398
extrude "Extrude9" cut of existing geometry blind -9.398
component_from_bodies "Body->Comp"
offset_faces "OffsetFaces1" distance 4.445
offset_faces "OffsetFaces2" distance -4.445
offset_faces "OffsetFaces3" distance 3.175
offset_faces "OffsetFaces4" distance 3.175
offset_faces "OffsetFaces5" distance 3.175
offset_faces "OffsetFaces6" distance -3.175
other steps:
base_feature "Base Feature" bodies "Plastic Insert"
create_component "CreateComponent1"
remove_body "RemoveBody1"
named bodies: "Plastic Insert"

design "Arca Tall"
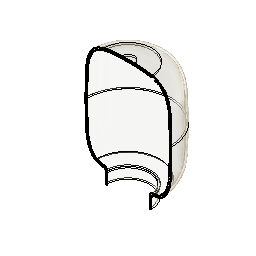
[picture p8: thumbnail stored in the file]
derived_base_feature "Derived Base Feature" bodies "Balon"
work_plane "WorkPlane1" AlongDistance 0
sketch "Sketch1" plane through (0, 0, 0) normal (0, 1, 0) x axis (1, 0, 0)
  line L1 (0, 317.5) -> (0, 2.9083)
  curve K1 (-82.9821, 124.2212) -> (-50.8, 237.8015)
  curve K2 (-51.0925, 237.681) -> (-50.8, 237.8015)
  curve K3 (-51.3855, 237.5558) -> (-51.0925, 237.681)
  curve K4 (-54.7608, 236.0513) -> (-51.3855, 237.5558)
  curve K5 (-57.9615, 234.05) -> (-54.7608, 236.0513)
  curve K6 (-67.2727, 226.749) -> (-57.9615, 234.05)
  curve K7 (-69.0552, 224.2615) -> (-67.2727, 226.749)
  curve K8 (-72.1872, 218.7832) -> (-69.0552, 224.2615)
  curve K9 (-74.1213, 215.1556) -> (-72.1872, 218.7832)
  curve K10 (-78.3031, 204.3965) -> (-74.1213, 215.1556)
  curve K11 (-79.7275, 197.3397) -> (-78.3031, 204.3965)
  curve K12 (-81.3333, 185.4664) -> (-79.7275, 197.3397)
  curve K13 (-81.6254, 178.4008) -> (-81.3333, 185.4664)
  curve K14 (-82.49, 152.2133) -> (-81.6254, 178.4008)
  curve K15 (-82.9821, 136.067) -> (-82.49, 152.2133)
  curve K16 (-82.9821, 124.2212) -> (-82.9821, 136.067)
  curve K17 (50.8, 237.7999) -> (82.9821, 124.2212)
  curve K18 (82.9821, 140.3031) -> (82.9821, 124.2212)
  curve K19 (81.9353, 169.4257) -> (82.9821, 140.3031)
  curve K20 (81.3621, 183.6489) -> (81.9353, 169.4257)
  curve K21 (80.9478, 189.8724) -> (81.3621, 183.6489)
  curve K22 (77.8147, 206.9858) -> (80.9478, 189.8724)
  curve K23 (74.9652, 213.2153) -> (77.8147, 206.9858)
  curve K24 (69.4688, 224.1531) -> (74.9652, 213.2153)
  curve K25 (67.2512, 226.458) -> (69.4688, 224.1531)
  curve K26 (61.5696, 231.3138) -> (67.2512, 226.458)
  curve K27 (57.377, 234.6711) -> (61.5696, 231.3138)
  curve K28 (52.0556, 237.2628) -> (57.377, 234.6711)
  curve K29 (51.4313, 237.5413) -> (52.0556, 237.2628)
  curve K30 (50.8, 237.7999) -> (51.4313, 237.5413)
  line L2 (-50.8, 317.5) -> (-50.8, 237.8015)
  line L3 (50.8, 317.5) -> (50.8, 237.7999)
  line L4 (-19.0713, 6.7501) -> (-19.0713, 6.7501)
  curve K31 (82.9821, 124.1958) -> (40.1509, 7.3012)
  curve K32 (41.8198, 7.6176) -> (40.1509, 7.3012)
  curve K33 (43.2113, 8.0663) -> (41.8198, 7.6176)
  curve K34 (47.0139, 9.2854) -> (43.2113, 8.0663)
  curve K35 (47.3314, 9.3805) -> (47.0139, 9.2854)
  curve K36 (50.1192, 10.3272) -> (47.3314, 9.3805)
  curve K37 (51.833, 11.0085) -> (50.1192, 10.3272)
  curve K38 (57.8313, 14.1895) -> (51.833, 11.0085)
  curve K39 (61.4491, 17.0488) -> (57.8313, 14.1895)
  curve K40 (66.8203, 21.5867) -> (61.4491, 17.0488)
  curve K41 (68.5372, 23.5528) -> (66.8203, 21.5867)
  curve K42 (71.2201, 27.8971) -> (68.5372, 23.5528)
  curve K43 (74.7424, 33.8984) -> (71.2201, 27.8971)
  curve K44 (78.2342, 44.8406) -> (74.7424, 33.8984)
  curve K45 (79.6792, 50.3463) -> (78.2342, 44.8406)
  curve K46 (81.3558, 63.5576) -> (79.6792, 50.3463)
  curve K47 (81.6386, 70.4415) -> (81.3558, 63.5576)
  curve K48 (82.4897, 96.2198) -> (81.6386, 70.4415)
  curve K49 (82.9814, 112.3523) -> (82.4897, 96.2198)
  curve K50 (82.9821, 124.1958) -> (82.9814, 112.3523)
  curve K51 (-40.1501, 7.301) -> (-82.9821, 124.1958)
  curve K52 (-82.9813, 110.5256) -> (-82.9821, 124.1958)
  curve K53 (-82.2545, 88.8594) -> (-82.9813, 110.5256)
  curve K54 (-81.6277, 70.519) -> (-82.2545, 88.8594)
  curve K55 (-81.3572, 64.3441) -> (-81.6277, 70.519)
  curve K56 (-79.4149, 46.8924) -> (-81.3572, 64.3441)
  curve K57 (-76.5204, 38.9768) -> (-79.4149, 46.8924)
  curve K58 (-73.5142, 32.2947) -> (-76.5204, 38.9768)
  curve K59 (-72.5556, 30.3818) -> (-73.5142, 32.2947)
  curve K60 (-69.7914, 25.3691) -> (-72.5556, 30.3818)
  curve K61 (-68.3824, 23.4028) -> (-69.7914, 25.3691)
  curve K62 (-64.5419, 19.5456) -> (-68.3824, 23.4028)
  curve K63 (-62.3002, 17.7646) -> (-64.5419, 19.5456)
  curve K64 (-53.6583, 11.1976) -> (-62.3002, 17.7646)
  curve K65 (-49.6968, 10.1396) -> (-53.6583, 11.1976)
  curve K66 (-43.4141, 8.1331) -> (-49.6968, 10.1396)
  curve K67 (-41.9704, 7.6516) -> (-43.4141, 8.1331)
  curve K68 (-40.1963, 7.3098) -> (-41.9704, 7.6516)
  curve K69 (-40.1732, 7.3054) -> (-40.1963, 7.3098)
  curve K70 (-40.1501, 7.301) -> (-40.1732, 7.3054)
  line L5 (-82.9821, 124.1958) -> (-82.9821, 124.2212)
  line L6 (82.9821, 124.2212) -> (82.9821, 124.1958)
  line L7 (0, 317.5) -> (-50.8, 317.5)
  line L8 (7.2015, 3.048) -> (0, 3.048)
  line L9 (0, 3.048) -> (-7.2015, 3.048)
  arc A1 centre (0, 188.595) radius 185.6867 clockwise from (-7.2015, 3.048) to (-40.1502, 7.301)
  arc A2 centre (0, 188.595) radius 185.6867 clockwise from (40.151, 7.3012) to (7.2015, 3.048)
  point P38 (-40.1502, 7.301)
  point P43 (40.1509, 7.3012)
  point P62 (-40.1501, 7.301)
  point P81 (40.151, 7.3012)
  point P84 (0, 3.048)
  vertical L1
  horizontal L4
  coincident P38 K51
  symmetric L1 A1 A2
  coincident A2 P43
  coincident A1 P62
  coincident K31 P81
  perpendicular L2 L7
  horizontal L8
  coincident L1 P84
  horizontal L9
revolve "Revolve1" sketch "Sketch1" AlongAngle 360
shell "Shell1" innerThickness 3.81
fillet "Fillet1" radius 6.35 bodies "Balon v3"
offset_faces "OffsetFaces1" distance -50.8
move "Move1"
move "Move2"
component_from_bodies "Body->Comp1"
component_from_bodies "Body->Comp2"
sketch "Sketch2" plane through (0, 0, 0) normal (0, 1, 0) x axis (1, 0, 0)
  line L1 (-85.5221, 124.2212) -> (-85.5221, 124.1961)
  curve K1 (-58.9057, 236.4383) -> (-50.8, 241.7989)
  curve K2 (-50.8, 241.554) -> (-50.8, 241.7989)
  curve K3 (-50.904, 240.933) -> (-50.8, 241.554)
  curve K4 (-51.2936, 240.2837) -> (-50.904, 240.933)
  curve K5 (-51.734, 239.7561) -> (-51.2936, 240.2837)
  curve K6 (-53.328, 238.5038) -> (-51.734, 239.7561)
  curve K7 (-54.0892, 238.1997) -> (-53.328, 238.5038)
  curve K8 (-58.9057, 236.4383) -> (-54.0892, 238.1997)
  curve K9 (-89.3309, 124.2212) -> (-58.9057, 236.4383)
  curve K10 (-62.6336, 234.9735) -> (-58.9057, 236.4383)
  curve K11 (-65.581, 233.1032) -> (-62.6336, 234.9735)
  curve K12 (-73.0224, 227.0019) -> (-65.581, 233.1032)
  curve K13 (-74.8981, 224.836) -> (-73.0224, 227.0019)
  curve K14 (-78.1104, 219.6097) -> (-74.8981, 224.836)
  curve K15 (-80.2663, 215.561) -> (-78.1104, 219.6097)
  curve K16 (-84.0943, 205.8277) -> (-80.2663, 215.561)
  curve K17 (-85.4655, 200.1154) -> (-84.0943, 205.8277)
  curve K18 (-87.4092, 188.5789) -> (-85.4655, 200.1154)
  curve K19 (-87.7349, 182.3889) -> (-87.4092, 188.5789)
  curve K20 (-88.4233, 165.9645) -> (-87.7349, 182.3889)
  curve K21 (-89.328, 138.6964) -> (-88.4233, 165.9645)
  curve K22 (-89.3309, 124.2212) -> (-89.328, 138.6964)
  line L2 (-89.3309, 124.1958) -> (-89.3309, 124.2212)
  curve K23 (-46.5001, 7.301) -> (-89.3309, 124.1958)
  curve K24 (-89.3314, 112.4293) -> (-89.3309, 124.1958)
  curve K25 (-88.8181, 95.3068) -> (-89.3314, 112.4293)
  curve K26 (-88.346, 81.2892) -> (-88.8181, 95.3068)
  curve K27 (-88.0298, 70.4902) -> (-88.346, 81.2892)
  curve K28 (-87.1514, 58.328) -> (-88.0298, 70.4902)
  curve K29 (-86.3326, 50.6119) -> (-87.1514, 58.328)
  curve K30 (-81.0932, 33.6688) -> (-86.3326, 50.6119)
  curve K31 (-77.3163, 27.4309) -> (-81.0932, 33.6688)
  curve K32 (-74.8955, 23.6666) -> (-77.3163, 27.4309)
  curve K33 (-73.5108, 22.0741) -> (-74.8955, 23.6666)
  curve K34 (-70.2346, 19.0457) -> (-73.5108, 22.0741)
  curve K35 (-64.8094, 14.3548) -> (-70.2346, 19.0457)
  curve K36 (-56.6696, 10.3041) -> (-64.8094, 14.3548)
  curve K37 (-54.0053, 9.483) -> (-56.6696, 10.3041)
  curve K38 (-49.1487, 7.9411) -> (-54.0053, 9.483)
  curve K39 (-48.3482, 7.6526) -> (-49.1487, 7.9411)
  curve K40 (-46.5001, 7.301) -> (-48.3482, 7.6526)
  line L3 (0, 266.7) -> (0, 0)
  line L4 (0, 3.048) -> (-7.7894, 3.048)
  line L5 (-50.8, 266.7) -> (-50.8, 241.7989)
  line L6 (0, 266.7) -> (-50.8, 266.7)
  arc A1 centre (-6.9779, 188.7329) radius 185.6867 clockwise from (-7.7894, 3.048) to (-46.5001, 7.301)
  point P1 (0, 0)
  point P44 (0, 0)
  point P46 (0, 3.048)
  point P5 (-50.8, 241.554)
  point P49 (0, 266.7)
  coincident P1 P44
  coincident L3 P46
  coincident P5 L5
  coincident L3 P49
revolve "Revolve2" sketch "Sketch2" AlongAngle 360 bodies "Balon v3"
shell "Shell2" innerThickness 3.81
component_from_bodies "Body->Comp3"
remove_instance "RemoveInstance1"
remove_instance "RemoveInstance2"
sketch "Sketch1" plane through (0, 0, 0) normal (0, 1, 0) x axis (1, 0, 0)
  line L1 (-6.35, 3.048) -> (-14.1394, 3.048)
  curve K1 (-52.8501, 7.301) -> (-95.6809, 124.1958)
  curve K2 (-95.6814, 112.4293) -> (-95.6809, 124.1958)
  curve K3 (-95.1681, 95.3068) -> (-95.6814, 112.4293)
  curve K4 (-94.696, 81.2892) -> (-95.1681, 95.3068)
  curve K5 (-94.3798, 70.4902) -> (-94.696, 81.2892)
  curve K6 (-93.5014, 58.328) -> (-94.3798, 70.4902)
  curve K7 (-92.6826, 50.6119) -> (-93.5014, 58.328)
  curve K8 (-87.4432, 33.6688) -> (-92.6826, 50.6119)
  curve K9 (-83.6663, 27.4309) -> (-87.4432, 33.6688)
  curve K10 (-81.2455, 23.6666) -> (-83.6663, 27.4309)
  curve K11 (-79.8608, 22.0741) -> (-81.2455, 23.6666)
  curve K12 (-76.5846, 19.0457) -> (-79.8608, 22.0741)
  curve K13 (-71.12, 13.97) -> (-76.5846, 19.0457)
  curve K14 (-62.23, 10.16) -> (-71.12, 13.97)
  curve K15 (-60.3553, 9.483) -> (-62.23, 10.16)
  curve K16 (-55.4987, 7.9411) -> (-60.3553, 9.483)
  curve K17 (-54.6982, 7.6526) -> (-55.4987, 7.9411)
  curve K18 (-52.8501, 7.301) -> (-54.6982, 7.6526)
  line L2 (-95.6809, 124.1958) -> (-95.6809, 124.2212)
  line L3 (0, 266.7) -> (0, 0)
  line L4 (0, 3.048) -> (-6.35, 3.048)
  line L5 (-95.6809, 124.2466) -> (-95.6809, 124.2212)
  line L6 (-50.8, 266.7) -> (-50.8, 241.7989)
  line L7 (0, 266.7) -> (-50.8, 266.7)
  curve K19 (-71.6837, 232.5587) -> (-50.8, 241.7989)
  curve K20 (-50.8, 237.8015) -> (-50.8, 241.7989)
  curve K21 (-53.6019, 236.5654) -> (-50.8, 237.8015)
  curve K22 (-59.7861, 236.0598) -> (-53.6019, 236.5654)
  curve K23 (-64.4375, 235.2772) -> (-59.7861, 236.0598)
  curve K24 (-69.8917, 233.4707) -> (-64.4375, 235.2772)
  curve K25 (-71.6837, 232.5587) -> (-69.8917, 233.4707)
  curve K26 (-71.6837, 232.5587) -> (-95.6809, 124.2466)
  curve K27 (-95.6814, 136.0132) -> (-95.6809, 124.2466)
  curve K28 (-95.1681, 153.1357) -> (-95.6814, 136.0132)
  curve K29 (-94.696, 167.1533) -> (-95.1681, 153.1357)
  curve K30 (-94.3798, 177.9523) -> (-94.696, 167.1533)
  curve K31 (-93.5014, 190.1145) -> (-94.3798, 177.9523)
  curve K32 (-92.6826, 197.8306) -> (-93.5014, 190.1145)
  curve K33 (-87.4432, 214.7737) -> (-92.6826, 197.8306)
  curve K34 (-83.6663, 221.0115) -> (-87.4432, 214.7737)
  curve K35 (-81.2455, 224.7759) -> (-83.6663, 221.0115)
  curve K36 (-79.8608, 226.3684) -> (-81.2455, 224.7759)
  curve K37 (-77.083, 228.9361) -> (-79.8608, 226.3684)
  curve K38 (-75.5537, 230.2778) -> (-77.083, 228.9361)
  curve K39 (-71.6837, 232.5587) -> (-75.5537, 230.2778)
  curve K40 (-50.8, 244.8458) -> (-50.8, 244.8469)
  curve K41 (-50.8, 244.8465) -> (-50.8, 244.8469)
  curve K42 (-50.8, 244.8462) -> (-50.8, 244.8465)
  curve K43 (-50.8, 244.8458) -> (-50.8, 244.8462)
  arc A1 centre (-13.3279, 188.7329) radius 185.6867 clockwise from (-14.1394, 3.048) to (-52.8501, 7.301)
  point P26 (0, 3.048)
  point P33 (-50.8, 237.8015)
  point P35 (-50.8, 237.8015)
  point P40 (-71.6837, 232.5587)
  point P53 (-50.8, 244.8458)
  coincident L3 P26
  perpendicular L3 L4
  coincident P33 P35
  coincident K19 P40
  coincident L6 P53
sketch "Sketch2" plane through (0, 0, 0) normal (0, 1, 0) x axis (1, 0, 0)
  line L1 (-95.6809, 124.1958) -> (-95.6809, 124.2212)
  line L2 (0, 266.7) -> (-50.8, 266.7)
  curve K1 (-58.9317, 239.3909) -> (-50.8, 244.8469)
  curve K2 (-50.8, 244.602) -> (-50.8, 244.8469)
  curve K3 (-50.904, 243.981) -> (-50.8, 244.602)
  curve K4 (-51.2936, 243.3317) -> (-50.904, 243.981)
  curve K5 (-51.734, 242.8041) -> (-51.2936, 243.3317)
  curve K6 (-53.328, 241.5518) -> (-51.734, 242.8041)
  curve K7 (-54.0892, 241.2477) -> (-53.328, 241.5518)
  curve K8 (-58.9317, 239.3909) -> (-54.0892, 241.2477)
  line L3 (-50.8, 266.7) -> (-50.8, 244.8458)
  curve K9 (-52.8501, 7.301) -> (-95.6809, 124.1958)
  curve K10 (-95.6814, 112.4293) -> (-95.6809, 124.1958)
  curve K11 (-95.1681, 95.3068) -> (-95.6814, 112.4293)
  curve K12 (-94.696, 81.2892) -> (-95.1681, 95.3068)
  curve K13 (-94.3798, 70.4902) -> (-94.696, 81.2892)
  curve K14 (-93.5014, 58.328) -> (-94.3798, 70.4902)
  curve K15 (-92.6826, 50.6119) -> (-93.5014, 58.328)
  curve K16 (-87.4432, 33.6688) -> (-92.6826, 50.6119)
  curve K17 (-83.6663, 27.4309) -> (-87.4432, 33.6688)
  curve K18 (-81.2455, 23.6666) -> (-83.6663, 27.4309)
  curve K19 (-79.8608, 22.0741) -> (-81.2455, 23.6666)
  curve K20 (-76.5846, 19.0457) -> (-79.8608, 22.0741)
  curve K21 (-73.7599, 16.6033) -> (-76.5846, 19.0457)
  curve K22 (-65.532, 11.7145) -> (-73.7599, 16.6033)
  curve K23 (-60.3553, 9.483) -> (-65.532, 11.7145)
  curve K24 (-55.4987, 7.9411) -> (-60.3553, 9.483)
  curve K25 (-54.6982, 7.6526) -> (-55.4987, 7.9411)
  curve K26 (-52.8501, 7.301) -> (-54.6982, 7.6526)
  line L4 (-95.6809, 124.2466) -> (-95.6809, 124.2212)
  line L5 (0, 3.048) -> (-6.35, 3.048)
  line L6 (-6.35, 3.048) -> (-14.1394, 3.048)
  curve K27 (-58.9317, 239.3909) -> (-95.6809, 124.2466)
  curve K28 (-95.6814, 136.0132) -> (-95.6809, 124.2466)
  curve K29 (-95.1681, 153.1357) -> (-95.6814, 136.0132)
  curve K30 (-94.696, 167.1533) -> (-95.1681, 153.1357)
  curve K31 (-94.3798, 177.9523) -> (-94.696, 167.1533)
  curve K32 (-93.5014, 190.1145) -> (-94.3798, 177.9523)
  curve K33 (-92.6826, 197.8306) -> (-93.5014, 190.1145)
  curve K34 (-87.4432, 214.7737) -> (-92.6826, 197.8306)
  curve K35 (-83.6663, 221.0115) -> (-87.4432, 214.7737)
  curve K36 (-81.2455, 224.7759) -> (-83.6663, 221.0115)
  curve K37 (-79.8608, 226.3684) -> (-81.2455, 224.7759)
  curve K38 (-76.5846, 229.3968) -> (-79.8608, 226.3684)
  curve K39 (-73.7599, 231.8391) -> (-76.5846, 229.3968)
  curve K40 (-65.833, 236.5491) -> (-73.7599, 231.8391)
  curve K41 (-61.4585, 238.4785) -> (-65.833, 236.5491)
  curve K42 (-58.9317, 239.3909) -> (-61.4585, 238.4785)
  line L7 (0, 3.048) -> (0, 266.7)
  arc A1 centre (-13.3279, 188.7329) radius 185.6867 clockwise from (-14.1394, 3.048) to (-52.8501, 7.301)
  point P52 (-50.8, 244.8458)
  coincident K1 P52
  perpendicular L5 L7
revolve "Revolve1" sketch "Sketch1" AlongAngle 360 bodies "Balon v3.3"
shell "Shell1" innerThickness 3.81
revolve "Revolve2" sketch "Sketch2" AlongAngle 360 bodies "Balon v3.2"
shell "Shell2" innerThickness 3.81
component_from_bodies "Body->Comp1"
component_from_bodies "Body->Comp2"
position "Position1"
remove_instance "RemoveInstance1" bodies "Balon v3"
remove_instance "RemoveInstance2"
move "Move1"
position "Position2" bodies "Balon v3"
sketch "Sketch3" plane through (0, 0, 0) normal (0, 1, 0) x axis (1, 0, 0)
  line L1 (0, 50.8) -> (0, -304.8)
  line L2 (127, 50.8) -> (127, -304.8)
  line L3 (-127, 50.8) -> (-127, -304.8)
  line L4 (139.7, 25.4) -> (-139.7, 25.4)
  line L5 (139.7, -292.1) -> (-139.7, -292.1)
  line L6 (95.25, 50.8) -> (95.25, -304.8)
  vertical L1
  dimension "d6" = 127
  dimension "d12" = -127
  dimension "d17" distance L4 L5 = 317.5
  dimension "d18" = 95.25
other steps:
base_feature "Base Feature1" bodies "Balon v3.3"
base_feature "Base Feature1" bodies "Balon v3.2"
base_feature "Base Feature1" bodies "Balon"
base_feature "Base Feature1" bodies "Balon v3"
base_feature "Base Feature1" bodies "Balon v2"
create_component "CreateComponent1"
remove_body "RemoveBody1"
create_component "CreateComponent2"
remove_body "RemoveBody2"
create_component "CreateComponent3"
remove_body "RemoveBody3" bodies "Balon v3"
create_component "CreateComponent1"
create_component "CreateComponent2"
remove_body "RemoveBody1" bodies "Balon v3"
create_component "CreateComponent3"
remove_body "RemoveBody2" bodies "Balon v3"
named bodies: "Balon", "Balon v2", "Balon v3", "Balon v3.3", "Balon v3.2"

design "Rubber Grommet"
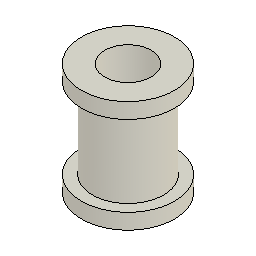
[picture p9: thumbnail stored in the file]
sketch "Sketch1" plane through (0, 0, 0) normal (0, 1, 0) x axis (1, 0, 0)
  line L1 (0, 3.048) -> (0, -12.7)
  line L2 (5.842, 0.508) -> (5.842, -12.7)
  line L3 (3.81, 3.048) -> (3.81, -15.24)
  line L4 (7.62, -12.7) -> (7.62, -15.24)
  line L5 (7.62, 3.048) -> (7.62, 0.508)
  line L6 (7.62, 0.508) -> (5.842, 0.508)
  line L7 (7.62, -12.7) -> (5.842, -12.7)
  line L8 (7.62, -15.24) -> (3.81, -15.24)
  line L9 (7.62, 3.048) -> (3.81, 3.048)
  vertical L1
  collinear L4 L5
revolve "Revolve1" sketch "Sketch1" AlongAngle 360 bodies "Rubber Grommet"
component_from_bodies "Body->Comp"
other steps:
base_feature "Base Feature" bodies "Rubber Grommet"
create_component "CreateComponent1"
remove_body "RemoveBody1"
named bodies: "Rubber Grommet"

design "Trove - TL"
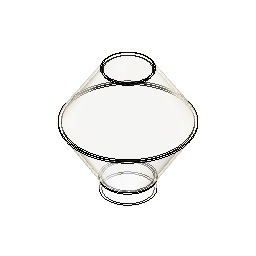
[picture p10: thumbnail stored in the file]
derived_base_feature "Derived Base Feature" bodies "Trove"
hole "Hole1" HoleDepth 88.9 HoleDiameter 44.45 TipAngle 118
sketch "Sketch1" plane through (0, 0, 0) normal (1, 0, 0) x axis (0, 1, 0)
  line L1 (0, 243.0601) -> (0, 247.8226)
  line L2 (-50.8, -12.7122) -> (-50.8, 10.9447)
  line L3 (0, -25.4) -> (0, 243.0601)
  line L4 (-46.0375, -12.7122) -> (-50.8, -12.7122)
  line L5 (-46.0375, -12.7122) -> (-46.0375, 12.3043)
  line L6 (-45.9716, 247.8226) -> (0, 247.8226)
  line L7 (-43.3841, 243.0601) -> (0, 243.0601)
  line L8 (-122.8321, 128.6352) -> (-51.757, 14.2971)
  line L9 (-117.1907, 128.5808) -> (-46.9945, 15.6567)
  line L10 (-48.6353, 246.3754) -> (-122.7993, 132.0392)
  line L11 (-46.0478, 241.6129) -> (-117.1579, 131.9848)
  arc A1 centre (-57.15, 10.9447) radius 6.35 clockwise from (-51.757, 14.2971) to (-50.8, 10.9447)
  arc A2 centre (-52.3875, 12.3043) radius 6.35 clockwise from (-46.9945, 15.6567) to (-46.0375, 12.3043)
  arc A3 centre (-114.4942, 130.257) radius 3.175 between (-117.1579, 131.9848) and (-117.1907, 128.5808)
  arc A4 centre (-120.1356, 130.3114) radius 3.175 between (-122.7993, 132.0392) and (-122.8321, 128.6352)
  arc A5 centre (-45.9716, 244.6476) radius 3.175 between (-45.9716, 247.8226) and (-48.6353, 246.3754)
  arc A6 centre (-43.3841, 239.8851) radius 3.175 clockwise from (-46.0478, 241.6129) to (-43.3841, 243.0601)
  point P3 (0, 247.8226)
  point P4 (0, 243.0601)
  vertical L1
  vertical L3
  tangent L5 A2
  perpendicular L1 L6
  perpendicular L1 L7
  tangent L11 A3
  tangent L9 A3
  tangent L10 A4
  tangent L8 A4
  equal A3 A4
  tangent L6 A5
  tangent L10 A5
  tangent L11 A6
  tangent L7 A6
  dimension "d8" distance P3 P4 = 4.7625
  dimension "d11" radius A2 = 6.35
  dimension "d15" radius A3 = 3.175
  dimension "d16" radius A5 = 3.175
  dimension "d17" radius A6 = 3.175
revolve "Revolve1" sketch "Sketch1" AlongAngle 180 bodies "Trove - TL"
revolve "Revolve2" sketch "Sketch1" AlongAngle -180
component_from_bodies "Body->Comp"
remove_body "RemoveBody2"
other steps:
base_feature "Base Feature" bodies "Trove - TL"
create_component "CreateComponent1"
remove_body "RemoveBody1"
named bodies: "Trove", "Trove - TL"

design "T9-5In"
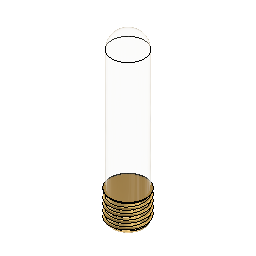
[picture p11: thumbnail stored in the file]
sketch "Sketch1" plane through (0, 0, 0) normal (0, 1, 0) x axis (1, 0, 0)
  line L1 (0, 0) -> (0, -127)
  line L2 (12.7, -127) -> (-12.7, -127)
  line L3 (12.7, -12.7) -> (12.7, -127)
  line L4 (-12.7, -127) -> (-12.7, -12.7)
  arc A1 centre (0, -12.7) radius 12.7 clockwise from (-12.7, -12.7) to (12.7, -12.7)
  point P1 (0, 0)
  point P3 (0, 0)
  coincident P1 P3
  vertical L1
  horizontal L2
  vertical L3
  vertical L4
revolve "Revolve1" sketch "Sketch1" AlongAngle 360 bodies "BU-T10-5-LED-120V"
derived_base_feature "Derived Base Feature" bodies "E26 Base"
move "Move1"
component_from_bodies "Body->Comp"
copy_paste "CutPaste"
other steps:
base_feature "Base Feature" bodies "BU-T10-5-LED-120V"
create_component "CreateComponent1"
create_component "CreateComponent2"
remove_body "RemoveBody1"
remove_instance "RemoveInstance1"
named bodies: "BU-T10-5-LED-120V", "E26 Base"
